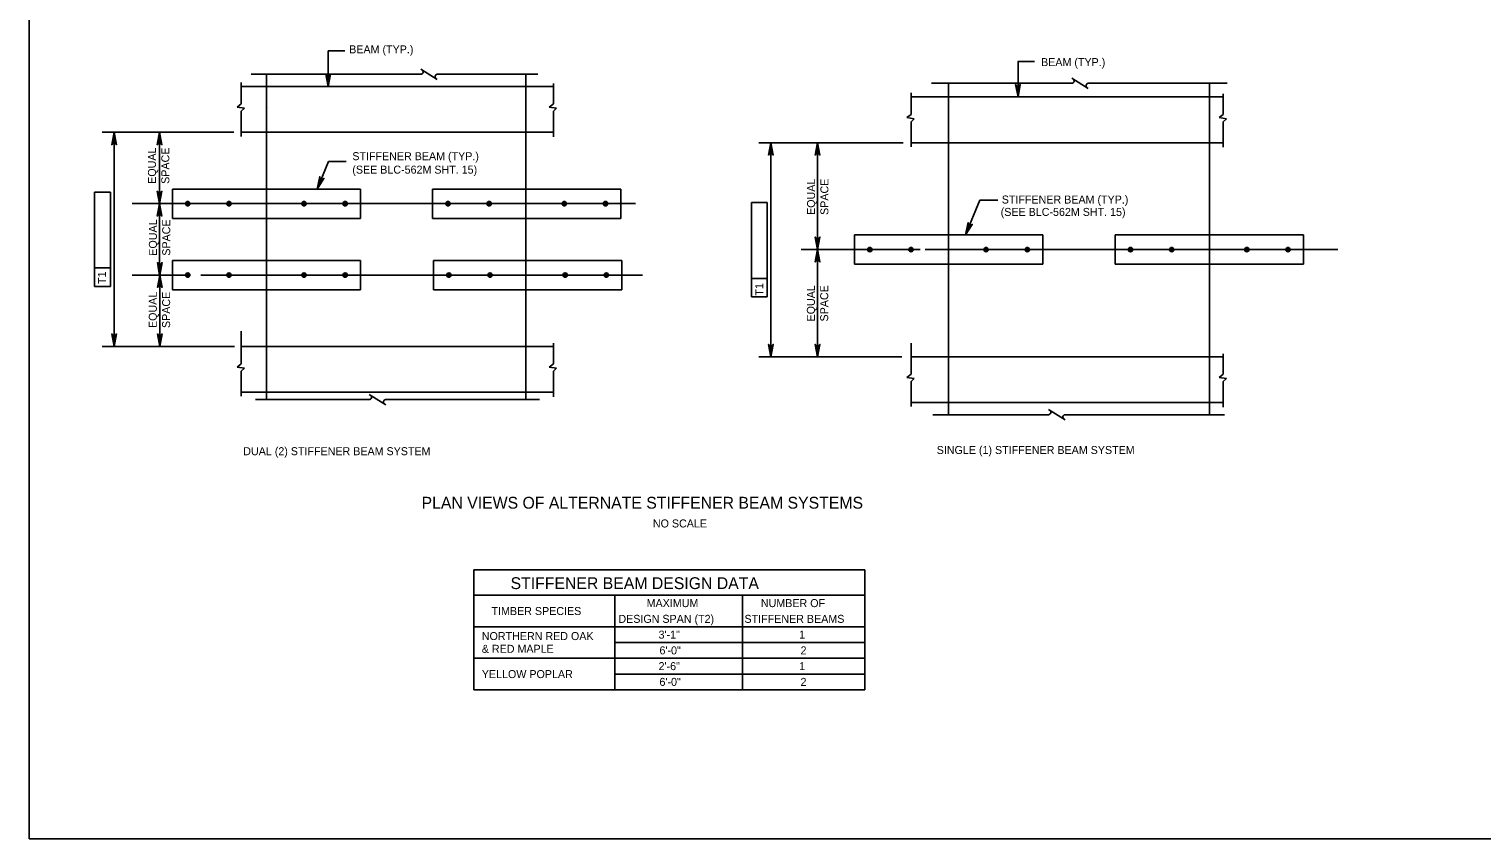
# Model space of a CAD drawing. Extents: x 638263 to 640391, y 293683 to 298655.
# Drawn here: x 639316 to 639861, y 295480 to 295784 of the extents above; entities that cross this region are included whole.
import ezdxf

# ---------------------------------------------------------------- set-up
doc = ezdxf.new("R2010")
doc.units = 0
for name, color, linetype in [('10', 7, 'Continuous'), ('2', 7, 'Continuous'), ('3', 7, 'Continuous'), ('4', 7, 'Continuous'), ('8', 7, 'Continuous')]:
    doc.layers.add(name, color=color, linetype=linetype)

msp = doc.modelspace()

# ---------------------------------------------------------------- linework, layer by layer
at = {"layer": '10'}
for p, q in [((639483.19, 295581.3), (639483.19, 295536.33)), ((639483.19, 295581.3), (639629.84, 295581.3)), ((639629.84, 295581.3), (639629.84, 295536.33)), ((639483.19, 295571.76), (639629.84, 295571.76)), ((639536.17, 295571.76), (639536.17, 295536.33)), ((639583.95, 295571.76), (639583.95, 295536.33)), ((639483.19, 295559.95), (639629.84, 295559.95)), ((639536.17, 295554.04), (639629.84, 295554.04)), ((639483.19, 295548.14), (639629.84, 295548.14)), ((639536.17, 295542.23), (639629.84, 295542.23)), ((639483.19, 295536.33), (639629.84, 295536.33))]:
    msp.add_line(p, q, dxfattribs=at)
at = {"layer": '2'}
for p, q in [((639316.46, 295480.46), (639316.46, 296044.46)), ((639405.49, 295645.1), (639405.49, 295767.05)), ((639502.74, 295645.1), (639502.74, 295767.05)), ((639661.25, 295639.44), (639661.25, 295763.63)), ((639759.08, 295639.44), (639759.08, 295763.63)), ((640102.46, 295480.46), (639316.46, 295480.46))]:
    msp.add_line(p, q, dxfattribs=at)
at = {"layer": '3'}
for p, q in [((639399.75, 295767.05), (639463.3, 295767.05)), ((639463.37, 295768.98), (639469.53, 295765.11)), ((639469.51, 295767.05), (639507.21, 295767.05)), ((639707.48, 295765.57), (639713.64, 295761.7)), ((639395.99, 295755.88), (639395.99, 295763.98)), ((639395.99, 295762.42), (639513.06, 295762.42)), ((639513.06, 295755.88), (639513.06, 295763.61)), ((639647.19, 295751.96), (639647.19, 295760.06)), ((639654.87, 295763.63), (639707.41, 295763.63)), ((639713.63, 295763.63), (639765.7, 295763.63)), ((639394.45, 295754.69), (639395.99, 295755.88)), ((639397.21, 295754.27), (639394.45, 295754.69)), ((639511.52, 295754.69), (639513.06, 295755.88)), ((639514.28, 295754.27), (639511.52, 295754.69)), ((639647.19, 295758.5), (639764.26, 295758.5)), ((639764.26, 295751.96), (639764.26, 295759.68)), ((639395.99, 295753.17), (639397.21, 295754.27)), ((639395.99, 295743.75), (639395.99, 295753.17)), ((639513.06, 295753.17), (639514.28, 295754.27)), ((639513.06, 295743.56), (639513.06, 295753.17)), ((639645.65, 295750.77), (639647.19, 295751.96)), ((639648.4, 295750.34), (639645.65, 295750.77)), ((639647.19, 295749.25), (639648.4, 295750.34)), ((639647.19, 295739.83), (639647.19, 295749.25)), ((639762.72, 295750.77), (639764.26, 295751.96)), ((639765.48, 295750.34), (639762.72, 295750.77)), ((639764.26, 295749.25), (639765.48, 295750.34)), ((639764.26, 295739.64), (639764.26, 295749.25)), ((639513.06, 295745.29), (639395.99, 295745.29)), ((639764.26, 295741.37), (639647.19, 295741.37)), ((639370.2, 295724.02), (639370.2, 295713)), ((639370.2, 295724.02), (639440.77, 295724.02)), ((639440.77, 295724.02), (639440.77, 295713)), ((639467.79, 295724.02), (639467.79, 295713)), ((639467.79, 295724.02), (639538.36, 295724.02)), ((639538.36, 295724.02), (639538.36, 295713)), ((639405.4, 295718.54), (639405.4, 295718.54)), ((639370.2, 295713), (639440.77, 295713)), ((639467.79, 295713), (639538.36, 295713)), ((639625.96, 295706.82), (639696.54, 295706.82)), ((639625.96, 295706.82), (639625.96, 295695.8)), ((639696.54, 295706.82), (639696.54, 295695.8)), ((639723.71, 295706.82), (639723.71, 295695.8)), ((639723.71, 295706.82), (639794.28, 295706.82)), ((639794.28, 295706.82), (639794.28, 295695.8)), ((639370.2, 295697.27), (639440.77, 295697.27)), ((639370.2, 295697.27), (639370.2, 295686.25)), ((639440.77, 295697.27), (639440.77, 295686.25)), ((639468.12, 295697.27), (639538.69, 295697.27)), ((639468.12, 295697.27), (639468.12, 295686.25)), ((639538.69, 295697.27), (639538.69, 295686.25)), ((639625.96, 295695.8), (639696.54, 295695.8)), ((639723.71, 295695.8), (639794.28, 295695.8)), ((639405.4, 295691.79), (639405.4, 295691.79)), ((639370.2, 295686.25), (639440.77, 295686.25)), ((639468.12, 295686.25), (639538.69, 295686.25)), ((639395.99, 295658.5), (639395.99, 295670.77)), ((639395.99, 295658.5), (639395.99, 295666.6)), ((639395.99, 295665.04), (639513.06, 295665.04)), ((639513.06, 295658.5), (639513.06, 295666.22)), ((639647.19, 295658.24), (639647.19, 295666.19)), ((639647.19, 295654.58), (639647.19, 295662.68)), ((639764.26, 295654.58), (639764.26, 295662.3)), ((639394.45, 295657.31), (639395.99, 295658.5)), ((639397.21, 295656.89), (639394.45, 295657.31)), ((639395.99, 295655.79), (639397.21, 295656.89)), ((639511.52, 295657.31), (639513.06, 295658.5)), ((639514.28, 295656.89), (639511.52, 295657.31)), ((639513.06, 295655.79), (639514.28, 295656.89)), ((639647.19, 295661.12), (639764.26, 295661.12)), ((639395.99, 295646.37), (639395.99, 295655.79)), ((639513.06, 295646.18), (639513.06, 295655.79)), ((639645.65, 295653.39), (639647.19, 295654.58)), ((639648.41, 295652.97), (639645.65, 295653.39)), ((639647.19, 295651.87), (639648.41, 295652.97)), ((639647.19, 295642.45), (639647.19, 295651.87)), ((639762.72, 295653.39), (639764.26, 295654.58)), ((639765.48, 295652.97), (639762.72, 295653.39)), ((639764.26, 295651.87), (639765.48, 295652.97)), ((639764.26, 295642.26), (639764.26, 295651.87)), ((639513.06, 295647.91), (639395.99, 295647.91)), ((639444.02, 295647.03), (639450.18, 295643.16)), ((639401.4, 295645.1), (639443.95, 295645.1)), ((639450.17, 295645.1), (639507.87, 295645.1)), ((639764.26, 295643.99), (639647.19, 295643.99)), ((639698.78, 295641.38), (639704.94, 295637.51)), ((639655.3, 295639.44), (639698.71, 295639.44)), ((639704.93, 295639.44), (639764.73, 295639.44))]:
    msp.add_line(p, q, dxfattribs=at)
for centre, radius in [((639375.96, 295718.51), 0.833), ((639375.96, 295718.51), 0.738), ((639375.96, 295718.51), 0.625), ((639375.96, 295718.51), 0.417), ((639375.96, 295718.51), 0.208), ((639391.41, 295718.51), 0.833), ((639391.41, 295718.51), 0.738), ((639391.41, 295718.51), 0.625), ((639391.41, 295718.51), 0.417), ((639391.41, 295718.51), 0.208), ((639419.56, 295718.51), 0.833), ((639419.56, 295718.51), 0.738), ((639419.56, 295718.51), 0.625), ((639419.56, 295718.51), 0.417), ((639419.56, 295718.51), 0.208), ((639435.01, 295718.51), 0.833), ((639435.01, 295718.51), 0.738), ((639435.01, 295718.51), 0.625), ((639435.01, 295718.51), 0.417), ((639435.01, 295718.51), 0.208), ((639473.55, 295718.51), 0.833), ((639473.55, 295718.51), 0.738), ((639473.55, 295718.51), 0.625), ((639473.55, 295718.51), 0.417), ((639473.55, 295718.51), 0.208), ((639489, 295718.51), 0.833), ((639489, 295718.51), 0.738), ((639489, 295718.51), 0.625), ((639489, 295718.51), 0.417), ((639489, 295718.51), 0.208), ((639517.15, 295718.51), 0.833), ((639517.15, 295718.51), 0.738), ((639517.15, 295718.51), 0.625), ((639517.15, 295718.51), 0.417), ((639517.15, 295718.51), 0.208), ((639532.6, 295718.51), 0.833), ((639532.6, 295718.51), 0.738), ((639532.6, 295718.51), 0.625), ((639532.6, 295718.51), 0.417), ((639532.6, 295718.51), 0.208), ((639631.72, 295701.31), 0.833), ((639631.72, 295701.31), 0.738), ((639631.72, 295701.31), 0.625), ((639631.72, 295701.31), 0.417), ((639631.72, 295701.31), 0.208), ((639647.17, 295701.31), 0.833), ((639647.17, 295701.31), 0.738), ((639647.17, 295701.31), 0.625), ((639647.17, 295701.31), 0.417), ((639647.17, 295701.31), 0.208), ((639675.32, 295701.31), 0.833), ((639675.32, 295701.31), 0.738), ((639675.32, 295701.31), 0.625), ((639675.32, 295701.31), 0.417), ((639675.32, 295701.31), 0.208), ((639690.78, 295701.31), 0.833), ((639690.78, 295701.31), 0.738), ((639690.78, 295701.31), 0.625), ((639690.78, 295701.31), 0.417), ((639690.78, 295701.31), 0.208), ((639729.47, 295701.31), 0.833), ((639729.47, 295701.31), 0.738), ((639729.47, 295701.31), 0.625), ((639729.47, 295701.31), 0.417), ((639729.47, 295701.31), 0.208), ((639744.92, 295701.31), 0.833), ((639744.92, 295701.31), 0.738), ((639744.92, 295701.31), 0.625), ((639744.92, 295701.31), 0.417), ((639744.92, 295701.31), 0.208), ((639773.07, 295701.31), 0.833), ((639773.07, 295701.31), 0.738), ((639773.07, 295701.31), 0.625), ((639773.07, 295701.31), 0.417), ((639773.07, 295701.31), 0.208), ((639788.52, 295701.31), 0.833), ((639788.52, 295701.31), 0.738), ((639788.52, 295701.31), 0.625), ((639788.52, 295701.31), 0.417), ((639788.52, 295701.31), 0.208), ((639375.96, 295691.76), 0.833), ((639375.96, 295691.76), 0.738), ((639375.96, 295691.76), 0.625), ((639375.96, 295691.76), 0.417), ((639375.96, 295691.76), 0.208), ((639391.41, 295691.76), 0.833), ((639391.41, 295691.76), 0.738), ((639391.41, 295691.76), 0.625), ((639391.41, 295691.76), 0.417), ((639391.41, 295691.76), 0.208), ((639419.56, 295691.76), 0.833), ((639419.56, 295691.76), 0.738), ((639419.56, 295691.76), 0.625), ((639419.56, 295691.76), 0.417), ((639419.56, 295691.76), 0.208), ((639435.01, 295691.76), 0.833), ((639435.01, 295691.76), 0.738), ((639435.01, 295691.76), 0.625), ((639435.01, 295691.76), 0.417), ((639435.01, 295691.76), 0.208), ((639473.88, 295691.76), 0.833), ((639473.88, 295691.76), 0.738), ((639473.88, 295691.76), 0.625), ((639473.88, 295691.76), 0.417), ((639473.88, 295691.76), 0.208), ((639489.33, 295691.76), 0.833), ((639489.33, 295691.76), 0.738), ((639489.33, 295691.76), 0.625), ((639489.33, 295691.76), 0.417), ((639489.33, 295691.76), 0.208), ((639517.48, 295691.76), 0.833), ((639517.48, 295691.76), 0.738), ((639517.48, 295691.76), 0.625), ((639517.48, 295691.76), 0.417), ((639517.48, 295691.76), 0.208), ((639532.93, 295691.76), 0.833), ((639532.93, 295691.76), 0.738), ((639532.93, 295691.76), 0.625), ((639532.93, 295691.76), 0.417), ((639532.93, 295691.76), 0.208)]:
    msp.add_circle(centre, radius, dxfattribs=at)
for centre, start, end in [((639463.3, 295767.96), 270, 60), ((639469.6, 295766.14), 95.3286, 237.8672), ((639707.41, 295764.54), 270, 60), ((639713.71, 295762.73), 95.3286, 237.8672), ((639443.95, 295646.01), 270, 60), ((639450.25, 295644.19), 95.3286, 237.8672), ((639698.71, 295640.35), 270, 60), ((639705.01, 295638.54), 95.3286, 237.8672)]:
    msp.add_arc(centre, 0.909, start, end, dxfattribs=at)
at = {"layer": '4'}
for p, q in [((639428.57, 295775.75), (639434.83, 295775.75)), ((639687.28, 295771.83), (639693.5, 295771.83)), ((639393.3, 295745.29), (639343.82, 295745.29)), ((639348.32, 295745.29), (639348.32, 295665.04)), ((639378.25, 295745.29), (639363.19, 295745.29)), ((639365.4, 295745.29), (639365.4, 295718.54)), ((639644.24, 295741.37), (639590.11, 295741.37)), ((639594.61, 295741.37), (639594.61, 295661.12)), ((639612.12, 295741.37), (639612.12, 295701.34)), ((639428.75, 295734.33), (639435.41, 295734.33)), ((639341.04, 295722.84), (639346.94, 295722.84)), ((639341.04, 295687.54), (639341.04, 295722.84)), ((639346.94, 295722.84), (639346.94, 295687.54)), ((639355.11, 295718.54), (639391.41, 295718.54)), ((639363.55, 295718.54), (639543.8, 295718.54)), ((639365.4, 295718.54), (639365.4, 295694.74)), ((639587.32, 295718.92), (639593.23, 295718.92)), ((639587.32, 295691.09), (639587.32, 295718.92)), ((639593.23, 295718.92), (639593.23, 295683.62)), ((639672.99, 295719.79), (639679.68, 295719.79)), ((639606, 295701.34), (639650.55, 295701.34)), ((639649.66, 295701.34), (639607.62, 295701.34)), ((639612.12, 295701.34), (639612.12, 295661.12)), ((639652.5, 295701.31), (639807.19, 295701.31)), ((639346.94, 295694.43), (639341.04, 295694.43)), ((639355.11, 295691.79), (639376.9, 295691.79)), ((639380.87, 295691.76), (639546.43, 295691.76)), ((639587.32, 295683.62), (639587.32, 295691.09)), ((639593.23, 295690.51), (639587.32, 295690.51)), ((639346.94, 295687.54), (639341.04, 295687.54)), ((639365.47, 295688.83), (639365.47, 295665.04)), ((639593.23, 295683.62), (639587.32, 295683.62)), ((639393.52, 295665.04), (639343.82, 295665.04)), ((639371.95, 295665.04), (639363.57, 295665.04)), ((639643.78, 295661.12), (639590.11, 295661.12))]:
    msp.add_line(p, q, dxfattribs=at)
for points in [[(639428.57, 295762.42), (639428.57, 295775.75)], [(639687.29, 295758.5), (639687.29, 295771.83)], [(639428.57, 295762.42), (639427.7, 295767.08), (639427.95, 295766.72), (639428.26, 295766.53), (639428.57, 295766.48), (639428.89, 295766.53), (639429.2, 295766.72), (639429.45, 295767.08), (639428.57, 295762.42), (639429.2, 295766.72), (639428.89, 295766.53), (639428.57, 295762.42), (639428.57, 295766.48), (639428.26, 295766.53), (639428.57, 295762.42), (639427.95, 295766.72)], [(639687.29, 295758.5), (639686.41, 295763.16), (639686.66, 295762.8), (639686.97, 295762.61), (639687.29, 295762.56), (639687.6, 295762.61), (639687.91, 295762.8), (639688.16, 295763.16), (639687.29, 295758.5), (639687.91, 295762.8), (639687.6, 295762.61), (639687.29, 295758.5), (639687.29, 295762.56), (639686.97, 295762.61), (639687.29, 295758.5), (639686.66, 295762.8)], [(639348.32, 295745.29), (639349.2, 295740.63), (639348.95, 295740.99), (639348.64, 295741.18), (639348.32, 295741.23), (639348.01, 295741.18), (639347.7, 295740.99), (639347.45, 295740.63), (639348.32, 295745.29), (639347.7, 295740.99), (639348.01, 295741.18), (639348.32, 295745.29), (639348.32, 295741.23), (639348.64, 295741.18), (639348.32, 295745.29), (639348.95, 295740.99)], [(639365.4, 295745.29), (639366.28, 295740.63), (639366.03, 295740.99), (639365.72, 295741.18), (639365.4, 295741.23), (639365.09, 295741.18), (639364.78, 295740.99), (639364.53, 295740.63), (639365.4, 295745.29), (639364.78, 295740.99), (639365.09, 295741.18), (639365.4, 295745.29), (639365.4, 295741.23), (639365.72, 295741.18), (639365.4, 295745.29), (639366.03, 295740.99)], [(639594.61, 295741.37), (639595.48, 295736.71), (639595.23, 295737.07), (639594.92, 295737.26), (639594.61, 295737.31), (639594.3, 295737.26), (639593.98, 295737.07), (639593.74, 295736.71), (639594.61, 295741.37), (639593.98, 295737.07), (639594.3, 295737.26), (639594.61, 295741.37), (639594.61, 295737.31), (639594.92, 295737.26), (639594.61, 295741.37), (639595.23, 295737.07)], [(639612.12, 295741.37), (639612.99, 295736.71), (639612.74, 295737.07), (639612.43, 295737.26), (639612.12, 295737.31), (639611.8, 295737.26), (639611.49, 295737.07), (639611.24, 295736.71), (639612.12, 295741.37), (639611.49, 295737.07), (639611.8, 295737.26), (639612.12, 295741.37), (639612.12, 295737.31), (639612.43, 295737.26), (639612.12, 295741.37), (639612.74, 295737.07)], [(639424.44, 295724.02), (639428.75, 295734.33)], [(639424.44, 295724.02), (639425.43, 295728.66), (639425.52, 295728.23), (639425.74, 295727.94), (639426.01, 295727.77), (639426.31, 295727.7), (639426.67, 295727.75), (639427.04, 295727.98), (639424.44, 295724.02), (639426.67, 295727.75), (639426.31, 295727.7), (639424.44, 295724.02), (639426.01, 295727.77), (639425.74, 295727.94), (639424.44, 295724.02), (639425.52, 295728.23)], [(639365.4, 295718.54), (639364.53, 295723.2), (639364.78, 295722.84), (639365.09, 295722.66), (639365.4, 295722.6), (639365.72, 295722.66), (639366.03, 295722.84), (639366.28, 295723.2), (639365.4, 295718.54), (639366.03, 295722.84), (639365.72, 295722.66), (639365.4, 295718.54), (639365.4, 295722.6), (639365.09, 295722.66), (639365.4, 295718.54), (639364.78, 295722.84)], [(639365.4, 295718.54), (639364.53, 295713.88), (639364.78, 295714.24), (639365.09, 295714.42), (639365.4, 295714.48), (639365.72, 295714.42), (639366.03, 295714.24), (639366.28, 295713.88), (639365.4, 295718.54), (639366.03, 295714.24), (639365.72, 295714.42), (639365.4, 295718.54), (639365.4, 295714.48), (639365.09, 295714.42), (639365.4, 295718.54), (639364.78, 295714.24)], [(639667.55, 295706.82), (639672.99, 295719.79)], [(639667.55, 295706.82), (639668.55, 295711.46), (639668.64, 295711.03), (639668.86, 295710.74), (639669.13, 295710.57), (639669.43, 295710.5), (639669.79, 295710.55), (639670.16, 295710.78), (639667.55, 295706.82), (639669.79, 295710.55), (639669.43, 295710.5), (639667.55, 295706.82), (639669.13, 295710.57), (639668.86, 295710.74), (639667.55, 295706.82), (639668.64, 295711.03)], [(639612.12, 295701.34), (639612.99, 295706), (639612.74, 295705.64), (639612.43, 295705.46), (639612.12, 295705.4), (639611.8, 295705.46), (639611.49, 295705.64), (639611.24, 295706), (639612.12, 295701.34), (639611.49, 295705.64), (639611.8, 295705.46), (639612.12, 295701.34), (639612.12, 295705.4), (639612.43, 295705.46), (639612.12, 295701.34), (639612.74, 295705.64)], [(639612.12, 295701.34), (639612.99, 295696.68), (639612.74, 295697.04), (639612.43, 295697.22), (639612.12, 295697.28), (639611.8, 295697.22), (639611.49, 295697.04), (639611.24, 295696.68), (639612.12, 295701.34), (639611.49, 295697.04), (639611.8, 295697.22), (639612.12, 295701.34), (639612.12, 295697.28), (639612.43, 295697.22), (639612.12, 295701.34), (639612.74, 295697.04)], [(639365.47, 295691.79), (639364.59, 295696.45), (639364.84, 295696.09), (639365.15, 295695.91), (639365.47, 295695.85), (639365.78, 295695.91), (639366.09, 295696.09), (639366.34, 295696.45), (639365.47, 295691.79), (639366.09, 295696.09), (639365.78, 295695.91), (639365.47, 295691.79), (639365.47, 295695.85), (639365.15, 295695.91), (639365.47, 295691.79), (639364.84, 295696.09)], [(639365.47, 295691.79), (639364.59, 295687.13), (639364.84, 295687.49), (639365.15, 295687.67), (639365.47, 295687.73), (639365.78, 295687.67), (639366.09, 295687.49), (639366.34, 295687.13), (639365.47, 295691.79), (639366.09, 295687.49), (639365.78, 295687.67), (639365.47, 295691.79), (639365.47, 295687.73), (639365.15, 295687.67), (639365.47, 295691.79), (639364.84, 295687.49)], [(639348.32, 295665.04), (639347.45, 295669.7), (639347.7, 295669.34), (639348.01, 295669.15), (639348.32, 295669.1), (639348.64, 295669.15), (639348.95, 295669.34), (639349.2, 295669.7), (639348.32, 295665.04), (639348.95, 295669.34), (639348.64, 295669.15), (639348.32, 295665.04), (639348.32, 295669.1), (639348.01, 295669.15), (639348.32, 295665.04), (639347.7, 295669.34)], [(639365.47, 295665.04), (639364.59, 295669.7), (639364.84, 295669.34), (639365.15, 295669.15), (639365.47, 295669.1), (639365.78, 295669.15), (639366.09, 295669.34), (639366.34, 295669.7), (639365.47, 295665.04), (639366.09, 295669.34), (639365.78, 295669.15), (639365.47, 295665.04), (639365.47, 295669.1), (639365.15, 295669.15), (639365.47, 295665.04), (639364.84, 295669.34)], [(639594.61, 295661.12), (639593.74, 295665.78), (639593.98, 295665.42), (639594.3, 295665.23), (639594.61, 295665.18), (639594.92, 295665.23), (639595.23, 295665.42), (639595.48, 295665.78), (639594.61, 295661.12), (639595.23, 295665.42), (639594.92, 295665.23), (639594.61, 295661.12), (639594.61, 295665.18), (639594.3, 295665.23), (639594.61, 295661.12), (639593.98, 295665.42)], [(639612.12, 295661.12), (639611.24, 295665.78), (639611.49, 295665.42), (639611.8, 295665.23), (639612.12, 295665.18), (639612.43, 295665.23), (639612.74, 295665.42), (639612.99, 295665.78), (639612.12, 295661.12), (639612.74, 295665.42), (639612.43, 295665.23), (639612.12, 295661.12), (639612.12, 295665.18), (639611.8, 295665.23), (639612.12, 295661.12), (639611.49, 295665.42)]]:
    msp.add_lwpolyline(points, dxfattribs=at)
for points in [[(639428.57, 295762.42), (639428.6, 295762.53), (639428.54, 295762.53)], [(639687.29, 295758.5), (639687.31, 295758.61), (639687.25, 295758.61)], [(639594.11, 295738.37), (639595.11, 295738.37), (639594.61, 295741.37)], [(639611.62, 295738.37), (639612.62, 295738.37), (639612.12, 295741.37)], [(639424.44, 295724.02), (639424.51, 295724.12), (639424.45, 295724.14)], [(639667.55, 295706.82), (639667.63, 295706.92), (639667.57, 295706.94)], [(639611.62, 295704.34), (639612.62, 295704.34), (639612.12, 295701.34)], [(639611.62, 295698.34), (639612.62, 295698.34), (639612.12, 295701.34)], [(639364.91, 295694.74), (639365.9, 295694.74), (639365.4, 295691.79)], [(639364.97, 295688.83), (639365.96, 295688.83), (639365.47, 295691.79)], [(639347.82, 295668.04), (639348.82, 295668.04), (639348.32, 295665.04)], [(639364.97, 295667.99), (639365.96, 295667.99), (639365.47, 295665.04)], [(639594.11, 295664.12), (639595.11, 295664.12), (639594.61, 295661.12)], [(639611.62, 295664.31), (639612.62, 295664.31), (639612.12, 295661.31)]]:
    msp.add_lwpolyline(points, close=True, dxfattribs=at)
at = {"layer": '8'}
for p, q in [((639406.27, 295754.52), (639406.27, 295754.52)), ((639406.28, 295754.55), (639406.28, 295754.55)), ((639405.4, 295718.54), (639405.4, 295718.54)), ((639405.4, 295691.79), (639405.4, 295691.79)), ((639405.49, 295657.14), (639405.49, 295657.14))]:
    msp.add_line(p, q, dxfattribs=at)

# ---------------------------------------------------------------- texts
at = {"layer": '4'}
for s, height, p in [('BEAM (TYP.)', 3, (639436.5, 295774.86)), ('BEAM (TYP.)', 3, (639695.94, 295770.07)), ('STIFFENER BEAM (TYP.)', 3, (639437.67, 295734.82)), ('(SEE BLC-562M SHT. 15)', 3, (639437.67, 295729.78)), ('(SEE BLC-562M SHT. 15)', 3, (639680.8, 295713.93)), ('STIFFENER BEAM (TYP.)', 3, (639681.2, 295718.58)), ('DUAL (2) STIFFENER BEAM SYSTEM', 3, (639396.78, 295624.26)), ('SINGLE (1) STIFFENER BEAM SYSTEM', 3, (639656.81, 295624.72)), ('PLAN VIEWS OF ALTERNATE STIFFENER BEAM SYSTEMS', 4.4292, (639463.64, 295604.23)), ('NO SCALE', 3, (639550.38, 295597.18)), ('STIFFENER BEAM DESIGN DATA', 4.4292, (639497.01, 295574.09)), ('MAXIMUM', 3, (639548.03, 295567.33)), ('NUMBER OF ', 3, (639590.87, 295567.33)), ('TIMBER SPECIES', 3, (639489.87, 295564.36)), ('DESIGN SPAN (T2)', 3, (639537.45, 295561.43)), ('STIFFENER BEAMS', 3, (639584.73, 295561.43)), ('3\'-1"', 3, (639552.51, 295555.52)), ('1', 3, (639605.22, 295555.52)), ('& RED MAPLE', 3, (639486.23, 295550.2)), ('NORTHERN RED OAK', 3, (639486.23, 295554.98)), ('6\'-0"', 3, (639552.85, 295549.62)), ('2', 3, (639605.75, 295549.62)), ('YELLOW POPLAR', 3, (639486.23, 295540.73)), ('2\'-6"', 3, (639552.51, 295543.71)), ('1', 3, (639605.22, 295543.71)), ('6\'-0"', 3, (639552.85, 295537.8)), ('2', 3, (639605.75, 295537.8))]:
    msp.add_text(s, height=height, dxfattribs=at).set_placement(p)
for p in [(639345.29, 295688.42), (639591.79, 295684.05)]:
    msp.add_text('T1', height=3, rotation=90, dxfattribs=at).set_placement(p)
at = {"layer": '8'}
for s, p in [('EQUAL ', (639364.05, 295725.96)), ('SPACE', (639369.05, 295725.95)), ('EQUAL ', (639611.18, 295714.3)), ('SPACE', (639616.18, 295714.3)), ('EQUAL ', (639364.39, 295699.02)), ('SPACE', (639369.39, 295699.02)), ('EQUAL ', (639364.35, 295671.92)), ('SPACE', (639369.35, 295671.91)), ('EQUAL ', (639611.12, 295674.37)), ('SPACE', (639616.12, 295674.37))]:
    msp.add_text(s, height=3, rotation=89.9708, dxfattribs=at).set_placement(p)

doc.saveas('drawing.dxf')
